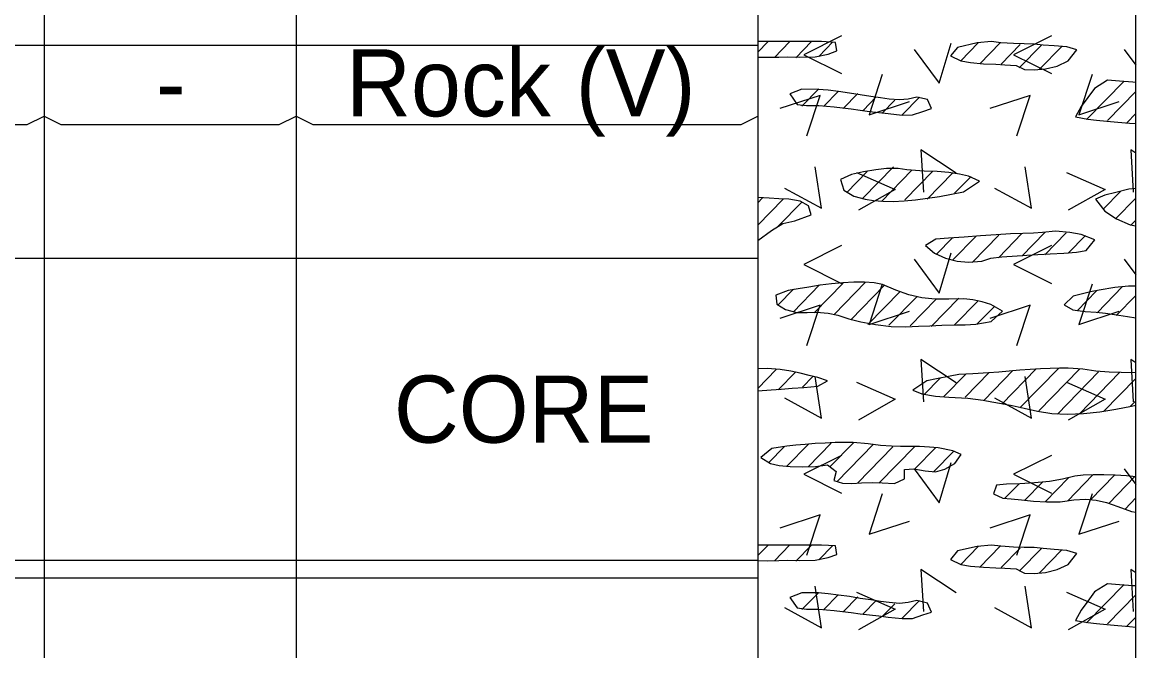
# Model space of a CAD drawing. Extents: x 0 to 0.833, y -0.32 to 0.608.
# Drawn here: x 0.7228 to 0.8333, y 0.0033 to 0.0658 of the extents above; entities that cross this region are included whole.
import ezdxf

# ---------------------------------------------------------------- set-up
doc = ezdxf.new("R2010")
doc.units = 0

msp = doc.modelspace()

# ---------------------------------------------------------------- linework, layer by layer
for points in [[(0, -0.32004), (0.83333, -0.32004), (0.83333, 0.60833), (0, 0.60833)], [(0.79583, 0.0623), (0.79676, 0.06229), (0.79792, 0.0623), (0.79882, 0.06234), (0.79992, 0.0623), (0.80151, 0.06234), (0.80282, 0.0626), (0.80367, 0.06292), (0.80354, 0.06376), (0.80216, 0.06384), (0.79583, 0.06384)], [(0.81822, 0.06165), (0.81944, 0.06159), (0.82033, 0.06155), (0.82145, 0.06148), (0.82229, 0.06107), (0.82324, 0.06103), (0.82438, 0.06113), (0.82555, 0.06142), (0.82662, 0.06192), (0.82749, 0.06302), (0.82651, 0.06332), (0.82524, 0.06342), (0.82413, 0.06349), (0.82324, 0.06359), (0.82226, 0.06361), (0.82121, 0.06364), (0.81995, 0.06373), (0.81902, 0.06384), (0.81761, 0.06371), (0.81566, 0.06326), (0.81496, 0.06242), (0.81598, 0.06193), (0.81695, 0.06176)], [(0.83305, 0.0598), (0.83171, 0.05991), (0.83054, 0.06001), (0.82925, 0.05919), (0.82857, 0.05828), (0.82792, 0.05739), (0.82735, 0.05636), (0.82858, 0.05614), (0.82945, 0.05604), (0.83045, 0.05594), (0.83155, 0.05584), (0.83272, 0.05575), (0.83333, 0.0557), (0.83333, 0.05979)], [(0.80066, 0.05749), (0.80188, 0.05749), (0.80339, 0.05736), (0.80423, 0.05726), (0.8051, 0.05715), (0.806, 0.05703), (0.80692, 0.05691), (0.80784, 0.0568), (0.80875, 0.05669), (0.81014, 0.05654), (0.81119, 0.05656), (0.81222, 0.0569), (0.81308, 0.05719), (0.81267, 0.05809), (0.8116, 0.05833), (0.81075, 0.05814), (0.80989, 0.05805), (0.80885, 0.05813), (0.80799, 0.05825), (0.80703, 0.05839), (0.806, 0.05855), (0.80492, 0.05872), (0.80384, 0.05888), (0.8028, 0.05901), (0.80182, 0.0591), (0.8002, 0.05911), (0.79901, 0.05864), (0.79974, 0.0576)], [(0.81233, 0.05099), (0.81063, 0.05111), (0.80977, 0.05124), (0.8086, 0.05125), (0.80755, 0.0511), (0.80632, 0.0509), (0.80513, 0.05066), (0.80403, 0.05014), (0.80436, 0.04908), (0.80536, 0.04851), (0.80647, 0.04821), (0.8073, 0.04806), (0.80824, 0.04799), (0.80926, 0.04798), (0.81035, 0.04803), (0.81149, 0.04813), (0.81267, 0.04828), (0.81386, 0.04846), (0.81506, 0.04868), (0.81625, 0.04891), (0.81783, 0.04999), (0.81673, 0.05049), (0.81585, 0.05069), (0.8148, 0.05085), (0.81361, 0.05095)], [(0.83265, 0.04918), (0.83136, 0.04887), (0.83028, 0.04859), (0.82934, 0.0482), (0.83026, 0.047), (0.83142, 0.04623), (0.83279, 0.04566), (0.83333, 0.04556), (0.83333, 0.04927)], [(0.79583, 0.04408), (0.79719, 0.04507), (0.79831, 0.04577), (0.79951, 0.04604), (0.80111, 0.04664), (0.80086, 0.04753), (0.80002, 0.048), (0.79889, 0.0482), (0.79791, 0.04823), (0.79694, 0.04828), (0.79583, 0.04837)], [(0.82537, 0.04502), (0.82408, 0.04487), (0.82319, 0.04482), (0.82214, 0.04479), (0.82091, 0.04475), (0.81947, 0.04466), (0.81792, 0.04454), (0.81632, 0.04442), (0.81475, 0.04433), (0.81348, 0.04423), (0.81247, 0.04359), (0.81337, 0.04283), (0.81444, 0.04232), (0.81561, 0.04204), (0.81675, 0.04193), (0.81807, 0.04204), (0.81896, 0.04232), (0.82003, 0.04246), (0.82157, 0.04258), (0.82253, 0.04264), (0.82362, 0.0427), (0.82483, 0.04276), (0.82618, 0.04283), (0.82745, 0.04294), (0.82842, 0.04311), (0.82927, 0.04417), (0.82791, 0.04468), (0.82679, 0.04488)], [(0.79885, 0.03911), (0.79763, 0.03865), (0.79773, 0.03776), (0.79859, 0.03723), (0.7997, 0.03694), (0.80074, 0.03695), (0.80165, 0.03696), (0.80281, 0.03688), (0.80377, 0.03667), (0.80486, 0.03632), (0.80606, 0.03602), (0.80751, 0.03575), (0.80905, 0.03556), (0.81052, 0.03553), (0.81177, 0.03559), (0.81289, 0.03563), (0.81408, 0.03567), (0.81553, 0.03571), (0.81642, 0.03573), (0.81745, 0.03577), (0.81897, 0.03604), (0.82011, 0.03707), (0.81896, 0.03774), (0.8181, 0.03801), (0.81717, 0.03821), (0.81626, 0.03831), (0.81479, 0.03825), (0.81343, 0.03826), (0.8121, 0.03841), (0.8108, 0.03871), (0.80953, 0.03917), (0.8082, 0.03972), (0.80736, 0.03988), (0.8064, 0.03995), (0.80536, 0.03995), (0.80427, 0.03989), (0.80314, 0.03978), (0.80201, 0.03964), (0.8009, 0.03947), (0.79984, 0.03929)], [(0.83263, 0.03956), (0.83126, 0.03942), (0.82969, 0.03916), (0.82883, 0.03898), (0.82712, 0.03857), (0.82623, 0.0377), (0.82708, 0.03721), (0.82831, 0.03703), (0.82941, 0.03696), (0.83033, 0.03687), (0.83165, 0.03669), (0.83253, 0.03655), (0.83333, 0.0364), (0.83333, 0.03955)], [(0.79583, 0.02916), (0.79715, 0.02927), (0.79814, 0.02934), (0.79922, 0.02942), (0.80039, 0.0295), (0.80179, 0.02962), (0.80275, 0.03014), (0.80179, 0.03048), (0.80091, 0.0307), (0.80003, 0.03092), (0.79909, 0.03112), (0.79803, 0.03129), (0.79677, 0.03138), (0.79583, 0.03136)], [(0.82816, 0.02691), (0.82978, 0.02708), (0.83137, 0.02733), (0.8329, 0.02764), (0.83333, 0.02775), (0.83333, 0.03099), (0.83295, 0.03095), (0.83188, 0.03098), (0.83071, 0.03103), (0.82938, 0.03113), (0.82807, 0.0313), (0.82662, 0.03142), (0.82576, 0.03142), (0.82484, 0.03139), (0.82387, 0.03134), (0.82286, 0.03128), (0.82182, 0.0312), (0.82077, 0.03111), (0.81973, 0.03103), (0.81872, 0.03095), (0.81715, 0.03086), (0.81579, 0.03077), (0.81491, 0.03063), (0.81357, 0.03036), (0.8126, 0.03015), (0.81121, 0.02923), (0.8121, 0.02886), (0.81345, 0.02862), (0.81479, 0.02853), (0.81668, 0.02843), (0.81818, 0.02823), (0.81905, 0.02808), (0.82, 0.0279), (0.82107, 0.02769), (0.82225, 0.02743), (0.82357, 0.02714), (0.82501, 0.02692), (0.82656, 0.02685)], [(0.79708, 0.02193), (0.79794, 0.02175), (0.79904, 0.02164), (0.80028, 0.0216), (0.80156, 0.02166), (0.80274, 0.02181), (0.80361, 0.02115), (0.80338, 0.02025), (0.80422, 0.01998), (0.80517, 0.01996), (0.80613, 0.02002), (0.8072, 0.02005), (0.80818, 0.02002), (0.80939, 0.01995), (0.81037, 0.02041), (0.81038, 0.02136), (0.8113, 0.02142), (0.81244, 0.02123), (0.81346, 0.02113), (0.81438, 0.02138), (0.81539, 0.02193), (0.81601, 0.02284), (0.81517, 0.02321), (0.81374, 0.02349), (0.81285, 0.02358), (0.81187, 0.02364), (0.81, 0.02364), (0.8091, 0.02366), (0.808, 0.02373), (0.80678, 0.02389), (0.8053, 0.02402), (0.80443, 0.02403), (0.80349, 0.02402), (0.80251, 0.02398), (0.80152, 0.02392), (0.80054, 0.02384), (0.79959, 0.02375), (0.7987, 0.02365), (0.79722, 0.02342), (0.79614, 0.02255)], [(0.83241, 0.02071), (0.83129, 0.02077), (0.83017, 0.02081), (0.8291, 0.02081), (0.82811, 0.02077), (0.82728, 0.02069), (0.82608, 0.02039), (0.82476, 0.02016), (0.8233, 0.02002), (0.82183, 0.01994), (0.82051, 0.01988), (0.81951, 0.01978), (0.81922, 0.01892), (0.82013, 0.0185), (0.82097, 0.01845), (0.822, 0.01835), (0.82318, 0.01822), (0.82448, 0.01813), (0.82584, 0.01815), (0.82719, 0.01832), (0.82836, 0.01839), (0.8294, 0.0183), (0.83043, 0.01807), (0.83156, 0.01768), (0.83291, 0.01719), (0.83333, 0.01711), (0.83333, 0.02063)], [(0.79583, 0.0123), (0.79676, 0.01229), (0.79792, 0.0123), (0.79882, 0.01234), (0.79992, 0.0123), (0.80151, 0.01234), (0.80282, 0.0126), (0.80367, 0.01292), (0.80354, 0.01376), (0.80216, 0.01384), (0.79583, 0.01384)], [(0.81822, 0.01165), (0.81944, 0.01159), (0.82033, 0.01155), (0.82145, 0.01148), (0.82229, 0.01107), (0.82324, 0.01103), (0.82438, 0.01113), (0.82555, 0.01142), (0.82662, 0.01192), (0.82749, 0.01302), (0.82651, 0.01332), (0.82524, 0.01342), (0.82413, 0.01349), (0.82324, 0.01359), (0.82226, 0.01361), (0.82121, 0.01364), (0.81995, 0.01373), (0.81902, 0.01384), (0.81761, 0.01371), (0.81566, 0.01326), (0.81496, 0.01242), (0.81598, 0.01193), (0.81695, 0.01176)], [(0.83305, 0.0098), (0.83171, 0.00991), (0.83054, 0.01001), (0.82925, 0.00919), (0.82857, 0.00828), (0.82792, 0.00739), (0.82735, 0.00636), (0.82858, 0.00614), (0.82945, 0.00604), (0.83045, 0.00594), (0.83155, 0.00584), (0.83272, 0.00575), (0.83333, 0.0057), (0.83333, 0.00979)], [(0.80066, 0.00749), (0.80188, 0.00749), (0.80339, 0.00736), (0.80423, 0.00726), (0.8051, 0.00715), (0.806, 0.00703), (0.80692, 0.00691), (0.80784, 0.0068), (0.80875, 0.00669), (0.81014, 0.00654), (0.81119, 0.00656), (0.81222, 0.0069), (0.81308, 0.00719), (0.81267, 0.00809), (0.8116, 0.00833), (0.81075, 0.00814), (0.80989, 0.00805), (0.80885, 0.00813), (0.80799, 0.00825), (0.80703, 0.00839), (0.806, 0.00855), (0.80492, 0.00872), (0.80384, 0.00888), (0.8028, 0.00901), (0.80182, 0.0091), (0.8002, 0.00911), (0.79901, 0.00864), (0.79974, 0.0076)]]:
    msp.add_lwpolyline(points, close=True)
for points in [[(0.725, 0.55417), (0.725, -0.27517)], [(0.75, 0.55417), (0.75, -0.27517)], [(0.75, 0.55417), (0.75, -0.27517)], [(0.79583, 0.55417), (0.79583, -0.27517)], [(0.725, 0.54167), (0.725, -0.27517)], [(0.83333, -0.27517), (0.83333, 0.50377)], [(0.80412, 0.06441), (0.80038, 0.06254), (0.80412, 0.06066)], [(0.82496, 0.06441), (0.82121, 0.06254), (0.82496, 0.06066)], [(0.70417, 0.0635), (0.725, 0.0635)], [(0.725, 0.0635), (0.75, 0.0635)], [(0.75, 0.0635), (0.79583, 0.0635)], [(0.79583, 0.06281), (0.79681, 0.06381)], [(0.79898, 0.06383), (0.79747, 0.06228)], [(0.80116, 0.06385), (0.79959, 0.06224)], [(0.80328, 0.06381), (0.80188, 0.06238)], [(0.81134, 0.06307), (0.81384, 0.0597), (0.81503, 0.0637)], [(0.8177, 0.06371), (0.81596, 0.06193)], [(0.81988, 0.06373), (0.81785, 0.06165)], [(0.82185, 0.06354), (0.81997, 0.06161)], [(0.824, 0.06353), (0.82178, 0.06125)], [(0.82601, 0.06337), (0.82378, 0.06109)], [(0.83217, 0.06307), (0.83333, 0.06151)], [(0.80818, 0.06058), (0.80687, 0.05658), (0.81087, 0.0579)], [(0.82901, 0.06058), (0.8277, 0.05658), (0.8317, 0.0579)], [(0.83217, 0.05992), (0.82844, 0.05611)], [(0.80188, 0.05915), (0.8002, 0.05743)], [(0.8038, 0.0589), (0.80237, 0.05744)], [(0.80575, 0.05869), (0.80429, 0.0572)], [(0.83333, 0.0589), (0.83052, 0.05602)], [(0.80069, 0.0545), (0.802, 0.0585), (0.798, 0.05719)], [(0.80758, 0.05835), (0.80627, 0.05701)], [(0.80941, 0.05802), (0.80816, 0.05674)], [(0.81188, 0.05833), (0.81016, 0.05658)], [(0.82152, 0.0545), (0.82284, 0.0585), (0.81884, 0.05719)], [(0.70417, 0.05644), (0.70583, 0.05562), (0.72333, 0.05562), (0.725, 0.05644)], [(0.725, 0.05644), (0.72667, 0.05562), (0.74833, 0.05562), (0.75, 0.05644)], [(0.75, 0.05644), (0.75167, 0.05562), (0.79417, 0.05562), (0.79583, 0.05644)], [(0.83333, 0.05669), (0.83245, 0.05579)], [(0.81551, 0.05078), (0.81201, 0.05309), (0.81226, 0.0489)], [(0.83333, 0.05277), (0.83284, 0.05309), (0.83309, 0.0489)], [(0.79847, 0.04929), (0.80215, 0.04729), (0.80153, 0.05142)], [(0.80465, 0.04887), (0.80667, 0.05095)], [(0.80562, 0.05084), (0.80946, 0.04916), (0.80581, 0.04709)], [(0.80626, 0.0483), (0.80928, 0.0514)], [(0.80809, 0.04797), (0.81111, 0.05107)], [(0.81041, 0.04814), (0.81318, 0.05097)], [(0.8193, 0.04929), (0.82299, 0.04729), (0.82236, 0.05142)], [(0.82645, 0.05084), (0.83029, 0.04916), (0.82664, 0.04709)], [(0.81264, 0.04821), (0.81518, 0.05081)], [(0.81536, 0.04878), (0.81699, 0.05045)], [(0.8301, 0.04721), (0.83184, 0.04899)], [(0.7963, 0.04833), (0.79583, 0.04784)], [(0.79834, 0.0482), (0.79583, 0.04563)], [(0.79786, 0.0455), (0.80023, 0.04792)], [(0.83131, 0.04623), (0.83333, 0.04831)], [(0.83285, 0.04561), (0.83333, 0.0461)], [(0.81519, 0.04439), (0.81354, 0.0427)], [(0.81514, 0.04213), (0.81748, 0.04453)], [(0.81709, 0.04191), (0.81974, 0.04463)], [(0.8197, 0.04237), (0.82203, 0.04477)], [(0.82202, 0.04253), (0.8243, 0.04487)], [(0.82431, 0.04267), (0.82644, 0.04486)], [(0.82663, 0.04283), (0.82834, 0.04458)], [(0.80412, 0.04358), (0.80038, 0.04171), (0.80412, 0.03983)], [(0.82496, 0.04358), (0.82121, 0.04171), (0.82496, 0.03983)], [(0.70417, 0.04233), (0.725, 0.04233)], [(0.725, 0.04233), (0.75, 0.04233)], [(0.75, 0.04233), (0.79583, 0.04233)], [(0.81134, 0.04224), (0.81384, 0.03887), (0.81503, 0.04287)], [(0.83217, 0.04224), (0.83333, 0.04068)], [(0.80142, 0.03692), (0.8043, 0.03987)], [(0.80653, 0.03994), (0.8034, 0.03673)], [(0.79938, 0.03925), (0.79786, 0.0377)], [(0.79933, 0.03699), (0.80195, 0.03968)], [(0.80506, 0.03622), (0.8084, 0.03964)], [(0.80997, 0.03904), (0.80675, 0.03574)], [(0.80818, 0.03975), (0.80687, 0.03575), (0.81087, 0.03706)], [(0.82751, 0.0371), (0.82945, 0.03908)], [(0.82901, 0.03975), (0.8277, 0.03575), (0.8317, 0.03706)], [(0.83203, 0.03951), (0.82949, 0.03691)], [(0.80069, 0.03367), (0.802, 0.03767), (0.798, 0.03636)], [(0.81164, 0.03854), (0.80884, 0.03567)], [(0.81353, 0.03826), (0.81094, 0.03561)], [(0.81303, 0.03554), (0.81579, 0.03837)], [(0.81534, 0.0357), (0.81768, 0.03809)], [(0.8176, 0.0358), (0.81934, 0.03758)], [(0.82152, 0.03367), (0.82284, 0.03767), (0.81884, 0.03636)], [(0.83138, 0.03663), (0.83333, 0.03863)], [(0.83333, 0.03642), (0.83333, 0.03642)], [(0.81551, 0.02994), (0.81201, 0.03226), (0.81226, 0.02807)], [(0.83333, 0.03193), (0.83284, 0.03226), (0.83309, 0.02807)], [(0.79765, 0.03127), (0.79583, 0.0294)], [(0.7996, 0.03105), (0.79786, 0.02927)], [(0.8164, 0.02853), (0.81879, 0.03098)], [(0.81829, 0.02825), (0.82114, 0.03117)], [(0.82004, 0.02783), (0.82346, 0.03133)], [(0.82569, 0.03141), (0.82184, 0.02747)], [(0.82775, 0.03131), (0.8237, 0.02716)], [(0.82964, 0.03104), (0.82557, 0.02686)], [(0.83173, 0.03097), (0.82774, 0.02688)], [(0.79847, 0.02846), (0.80215, 0.02646), (0.80153, 0.03059)], [(0.8013, 0.03058), (0.80027, 0.02952)], [(0.80562, 0.03001), (0.80946, 0.02832), (0.80581, 0.02626)], [(0.81392, 0.03042), (0.81235, 0.02881)], [(0.8143, 0.02859), (0.8165, 0.03084)], [(0.8193, 0.02846), (0.82299, 0.02646), (0.82236, 0.03059)], [(0.82645, 0.03001), (0.83029, 0.02832), (0.82664, 0.02626)], [(0.83333, 0.03039), (0.83012, 0.0271)], [(0.83281, 0.02764), (0.83333, 0.02818)], [(0.79844, 0.02361), (0.79691, 0.02204)], [(0.79871, 0.02167), (0.80085, 0.02386)], [(0.80083, 0.02163), (0.80311, 0.02397)], [(0.80534, 0.02404), (0.80299, 0.02163)], [(0.80367, 0.02011), (0.80732, 0.02386)], [(0.80571, 0.02), (0.80924, 0.02361)], [(0.81142, 0.02363), (0.80785, 0.01998)], [(0.81141, 0.0214), (0.81348, 0.02353)], [(0.80412, 0.02275), (0.80038, 0.02087), (0.80412, 0.019)], [(0.81528, 0.02316), (0.81331, 0.02114)], [(0.82496, 0.02275), (0.82121, 0.02087), (0.82496, 0.019)], [(0.81134, 0.02141), (0.81384, 0.01803), (0.81503, 0.02203)], [(0.83217, 0.02141), (0.83333, 0.01985)], [(0.82035, 0.01849), (0.82176, 0.01994)], [(0.82233, 0.01831), (0.82408, 0.0201)], [(0.82433, 0.01814), (0.82666, 0.02053)], [(0.82909, 0.02081), (0.82656, 0.01822)], [(0.82885, 0.01835), (0.83122, 0.02078)], [(0.83325, 0.02064), (0.83065, 0.01798)], [(0.80818, 0.01892), (0.80687, 0.01492), (0.81087, 0.01623)], [(0.82901, 0.01892), (0.8277, 0.01492), (0.8317, 0.01623)], [(0.83333, 0.01852), (0.83227, 0.01742)], [(0.80069, 0.01284), (0.802, 0.01684), (0.798, 0.01552)], [(0.82152, 0.01284), (0.82284, 0.01684), (0.81884, 0.01552)], [(0.79583, 0.01281), (0.79681, 0.01381)], [(0.79898, 0.01383), (0.79747, 0.01228)], [(0.80116, 0.01385), (0.79959, 0.01224)], [(0.80328, 0.01381), (0.80188, 0.01238)], [(0.8177, 0.01371), (0.81596, 0.01193)], [(0.81988, 0.01373), (0.81785, 0.01165)], [(0.82185, 0.01354), (0.81997, 0.01161)], [(0.824, 0.01353), (0.82178, 0.01125)], [(0.82601, 0.01337), (0.82378, 0.01109)], [(0.70417, 0.01235), (0.725, 0.01235)], [(0.725, 0.01235), (0.75, 0.01235)], [(0.75, 0.01235), (0.79583, 0.01235)], [(0.81551, 0.00911), (0.81201, 0.01142), (0.81226, 0.00724)], [(0.83333, 0.0111), (0.83284, 0.01142), (0.83309, 0.00724)], [(0.70417, 0.01058), (0.725, 0.01058)], [(0.725, 0.01058), (0.75, 0.01058)], [(0.75, 0.01058), (0.79583, 0.01058)], [(0.79847, 0.00763), (0.80215, 0.00563), (0.80153, 0.00975)], [(0.80188, 0.00915), (0.8002, 0.00743)], [(0.8038, 0.0089), (0.80237, 0.00744)], [(0.80562, 0.00917), (0.80946, 0.00749), (0.80581, 0.00543)], [(0.8193, 0.00763), (0.82299, 0.00563), (0.82236, 0.00975)], [(0.82645, 0.00917), (0.83029, 0.00749), (0.82664, 0.00543)], [(0.83217, 0.00992), (0.82844, 0.00611)], [(0.83333, 0.0089), (0.83052, 0.00602)], [(0.80575, 0.00869), (0.80429, 0.0072)], [(0.80758, 0.00835), (0.80627, 0.00701)], [(0.80941, 0.00802), (0.80816, 0.00674)], [(0.81188, 0.00833), (0.81016, 0.00658)], [(0.83333, 0.00669), (0.83245, 0.00579)]]:
    msp.add_lwpolyline(points)

# ---------------------------------------------------------------- texts
for s, height, p in [('Rock (V)', 0.006667, (0.75497, 0.05642)), ('-', 0.00667, (0.73609, 0.05642)), ('CORE', 0.006667, (0.75971, 0.02401))]:
    msp.add_text(s, height=height).set_placement(p)

doc.saveas('drawing.dxf')
